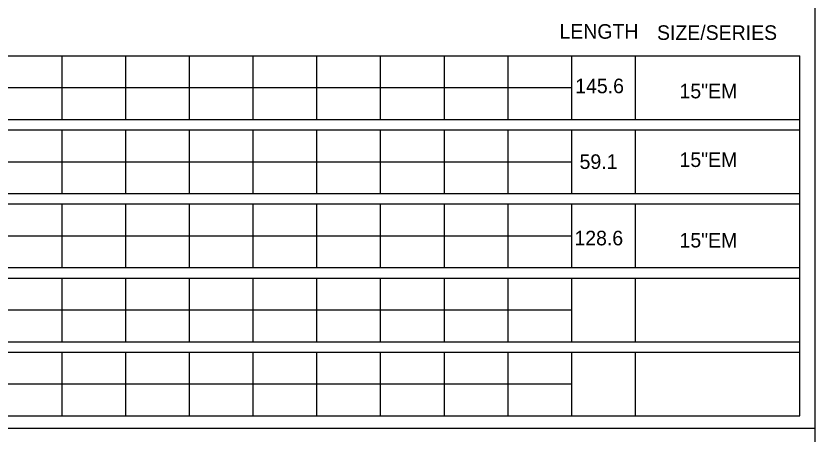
# Model space of a CAD drawing. Extents: x 10268147 to 10268469, y 2141099 to 2141204.
# Drawn here: x 10268267.89 to 10268306.32, y 2141156.92 to 2141177.01 of the extents above; entities that cross this region are included whole.
import ezdxf

# ---------------------------------------------------------------- set-up
doc = ezdxf.new("R2010")
doc.units = 0
for name, color, linetype in [('61', 7, 'Continuous'), ('GSDims', 7, 'Continuous'), ('North Arrow', 7, 'Continuous'), ('SheetLinesMisc2_dp', 7, 'Continuous'), ('TextMisc', 7, 'Continuous')]:
    doc.layers.add(name, color=color, linetype=linetype)

msp = doc.modelspace()

# ---------------------------------------------------------------- linework, layer by layer
at = {"layer": '61'}
for p, q in [((10268230.252, 2141175.094), (10268305.587, 2141175.094)), ((10268270.092, 2141175.094), (10268270.092, 2141172.034)), ((10268270.092, 2141175.094), (10268270.092, 2141172.034)), ((10268273.157, 2141175.094), (10268273.157, 2141172.034)), ((10268273.157, 2141175.094), (10268273.157, 2141172.034)), ((10268276.221, 2141175.094), (10268276.221, 2141172.034)), ((10268276.221, 2141175.094), (10268276.221, 2141172.034)), ((10268279.285, 2141175.094), (10268279.285, 2141172.034)), ((10268279.285, 2141175.094), (10268279.285, 2141172.034)), ((10268282.35, 2141175.094), (10268282.35, 2141172.034)), ((10268282.35, 2141175.094), (10268282.35, 2141172.034)), ((10268285.415, 2141175.094), (10268285.415, 2141172.034)), ((10268285.415, 2141175.094), (10268285.415, 2141172.034)), ((10268288.48, 2141175.094), (10268288.48, 2141172.034)), ((10268288.48, 2141175.094), (10268288.48, 2141172.034)), ((10268291.544, 2141175.094), (10268291.544, 2141172.034)), ((10268291.544, 2141175.094), (10268291.544, 2141172.034)), ((10268294.609, 2141175.094), (10268294.609, 2141172.034)), ((10268294.609, 2141175.094), (10268294.609, 2141172.034)), ((10268297.674, 2141175.094), (10268297.674, 2141172.034)), ((10268297.674, 2141175.094), (10268297.674, 2141172.034)), ((10268305.587, 2141157.796), (10268305.587, 2141175.094)), ((10268230.252, 2141173.564), (10268294.609, 2141173.564)), ((10268230.252, 2141173.564), (10268294.609, 2141173.564)), ((10268230.252, 2141172.034), (10268305.587, 2141172.034)), ((10268230.252, 2141171.535), (10268305.587, 2141171.535)), ((10268270.092, 2141171.535), (10268270.092, 2141168.475)), ((10268270.092, 2141171.535), (10268270.092, 2141168.475)), ((10268273.157, 2141171.535), (10268273.157, 2141168.475)), ((10268273.157, 2141171.535), (10268273.157, 2141168.475)), ((10268276.221, 2141171.535), (10268276.221, 2141168.475)), ((10268276.221, 2141171.535), (10268276.221, 2141168.475)), ((10268279.285, 2141171.535), (10268279.285, 2141168.475)), ((10268279.285, 2141171.535), (10268279.285, 2141168.475)), ((10268282.35, 2141171.535), (10268282.35, 2141168.475)), ((10268282.35, 2141171.535), (10268282.35, 2141168.475)), ((10268285.415, 2141171.535), (10268285.415, 2141168.475)), ((10268285.415, 2141171.535), (10268285.415, 2141168.475)), ((10268288.48, 2141171.535), (10268288.48, 2141168.475)), ((10268288.48, 2141171.535), (10268288.48, 2141168.475)), ((10268291.544, 2141171.535), (10268291.544, 2141168.475)), ((10268291.544, 2141171.535), (10268291.544, 2141168.475)), ((10268294.609, 2141171.535), (10268294.609, 2141168.475)), ((10268294.609, 2141171.535), (10268294.609, 2141168.475)), ((10268297.674, 2141171.535), (10268297.674, 2141168.475)), ((10268297.674, 2141171.535), (10268297.674, 2141168.475)), ((10268230.252, 2141170.005), (10268294.609, 2141170.005)), ((10268230.252, 2141170.005), (10268294.609, 2141170.005)), ((10268230.252, 2141168.475), (10268305.587, 2141168.475)), ((10268230.252, 2141167.976), (10268305.587, 2141167.976)), ((10268270.092, 2141167.976), (10268270.092, 2141164.915)), ((10268270.092, 2141167.976), (10268270.092, 2141164.915)), ((10268273.157, 2141167.976), (10268273.157, 2141164.915)), ((10268273.157, 2141167.976), (10268273.157, 2141164.915)), ((10268276.221, 2141167.976), (10268276.221, 2141164.915)), ((10268276.221, 2141167.976), (10268276.221, 2141164.915)), ((10268279.285, 2141167.976), (10268279.285, 2141164.915)), ((10268279.285, 2141167.976), (10268279.285, 2141164.915)), ((10268282.35, 2141167.976), (10268282.35, 2141164.915)), ((10268282.35, 2141167.976), (10268282.35, 2141164.915)), ((10268285.415, 2141167.976), (10268285.415, 2141164.915)), ((10268285.415, 2141167.976), (10268285.415, 2141164.915)), ((10268288.48, 2141167.976), (10268288.48, 2141164.915)), ((10268288.48, 2141167.976), (10268288.48, 2141164.915)), ((10268291.544, 2141167.976), (10268291.544, 2141164.915)), ((10268291.544, 2141167.976), (10268291.544, 2141164.915)), ((10268294.609, 2141167.976), (10268294.609, 2141164.915)), ((10268294.609, 2141167.976), (10268294.609, 2141164.915)), ((10268297.674, 2141167.976), (10268297.674, 2141164.915)), ((10268297.674, 2141167.976), (10268297.674, 2141164.915)), ((10268230.252, 2141166.445), (10268294.609, 2141166.445)), ((10268230.252, 2141166.445), (10268294.609, 2141166.445)), ((10268230.252, 2141164.915), (10268305.587, 2141164.915)), ((10268230.252, 2141164.416), (10268305.587, 2141164.416)), ((10268270.092, 2141164.416), (10268270.092, 2141161.355)), ((10268273.157, 2141164.416), (10268273.157, 2141161.355)), ((10268276.221, 2141164.416), (10268276.221, 2141161.355)), ((10268279.285, 2141164.416), (10268279.285, 2141161.355)), ((10268282.35, 2141164.416), (10268282.35, 2141161.355)), ((10268285.415, 2141164.416), (10268285.415, 2141161.355)), ((10268288.48, 2141164.416), (10268288.48, 2141161.355)), ((10268291.544, 2141164.416), (10268291.544, 2141161.355)), ((10268294.609, 2141164.416), (10268294.609, 2141161.355)), ((10268297.674, 2141164.416), (10268297.674, 2141161.355)), ((10268230.252, 2141162.886), (10268294.609, 2141162.886)), ((10268230.252, 2141161.355), (10268305.587, 2141161.355)), ((10268230.252, 2141160.856), (10268305.587, 2141160.856)), ((10268270.092, 2141160.856), (10268270.092, 2141157.796)), ((10268273.157, 2141160.856), (10268273.157, 2141157.796)), ((10268276.221, 2141160.856), (10268276.221, 2141157.796)), ((10268279.285, 2141160.856), (10268279.285, 2141157.796)), ((10268282.35, 2141160.856), (10268282.35, 2141157.796)), ((10268285.415, 2141160.856), (10268285.415, 2141157.796)), ((10268288.48, 2141160.856), (10268288.48, 2141157.796)), ((10268291.544, 2141160.856), (10268291.544, 2141157.796)), ((10268294.609, 2141160.856), (10268294.609, 2141157.796)), ((10268297.674, 2141160.856), (10268297.674, 2141157.796)), ((10268230.252, 2141159.327), (10268294.609, 2141159.327)), ((10268230.252, 2141157.796), (10268305.587, 2141157.796))]:
    msp.add_line(p, q, dxfattribs=at)
at = {"layer": 'SheetLinesMisc2_dp'}
for p, q in [((10268306.32, 2141108.602), (10268306.32, 2141203.954)), ((10268153.14, 2141157.195), (10268306.32, 2141157.195))]:
    msp.add_line(p, q, dxfattribs=at)

# ---------------------------------------------------------------- texts
at = {"layer": 'GSDims'}
for p in [(10268299.804, 2141173.05), (10268299.804, 2141169.752), (10268299.804, 2141165.883)]:
    msp.add_text('15"EM', height=0.7, dxfattribs=at).set_placement(p)
at = {"layer": 'North Arrow'}
for s, p in [('145.6', (10268294.789, 2141173.296)), ('59.1', (10268294.998, 2141169.659)), ('128.6', (10268294.75, 2141165.987))]:
    msp.add_text(s, height=0.7, dxfattribs=at).set_placement(p)
at = {"layer": 'TextMisc'}
for s, p in [('LENGTH', (10268294.033, 2141175.914)), ('SIZE/SERIES', (10268298.721, 2141175.858))]:
    msp.add_text(s, height=0.7, dxfattribs=at).set_placement(p)

doc.saveas('drawing.dxf')
